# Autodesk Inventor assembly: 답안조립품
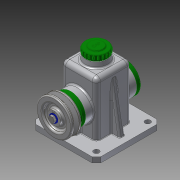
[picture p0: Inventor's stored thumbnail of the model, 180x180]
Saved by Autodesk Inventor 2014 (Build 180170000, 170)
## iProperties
Created: 2017-08
Part Number: 답안조립품
Document SubType Name: Assembly
Designer: user
Author: user
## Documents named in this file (14)
- D:\470825V1007\답안조립품.iam
- D:\470825V1007\본체.ipt
- D:\470825V1007\뒤커버.ipt
- D:\470825V1007\베어링 15 x 35 x 11.ipt
- D:\470825V1007\앞커버.ipt
- D:\470825V1007\오일실 15 25 7.ipt
- D:\470825V1007\멈춤링 15 x 1.ipt
- D:\470825V1007\축.ipt
- D:\470825V1007\볼트 M4 x 10.ipt
- D:\470825V1007\키 5 x 5 x 14.ipt
- D:\470825V1007\V-벨트풀리.ipt
- D:\470825V1007\와셔.ipt
- D:\470825V1007\볼트 M6 x 12.ipt
- D:\470825V1007\상부캡.ipt
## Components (1 placed, 1 different names)
1. V-벨트풀리:1 — 각도:2
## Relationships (1: Angle 1)
- 각도:2 [Angle]: V-벨트풀리:1
